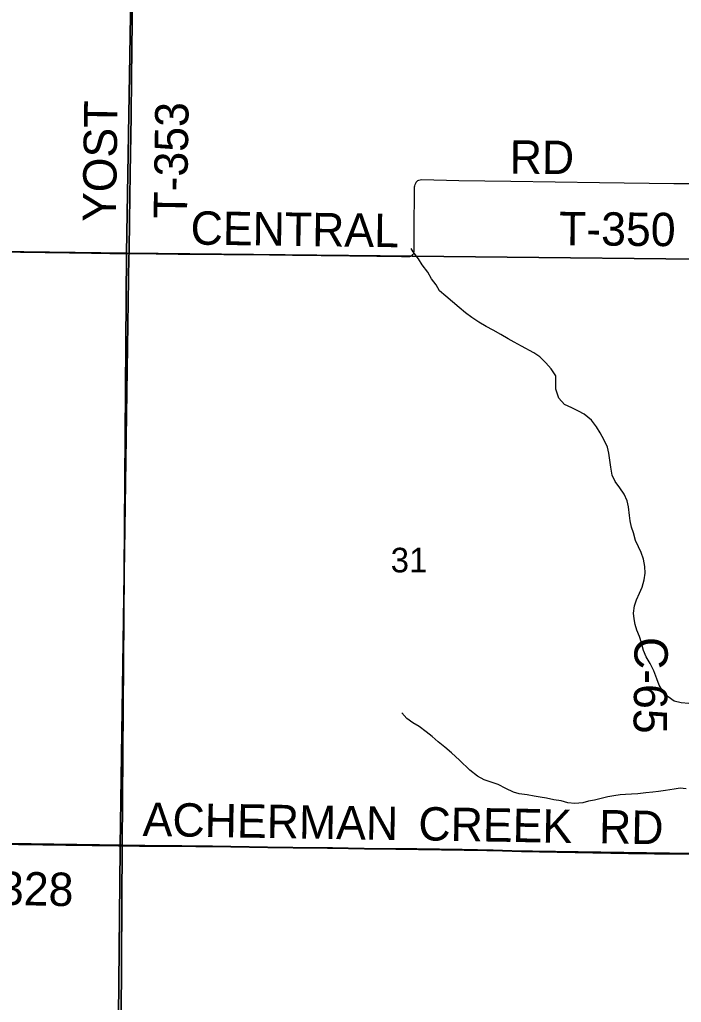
# Model space of a CAD drawing. Extents: x 0 to 34, y 0 to 22.
# Drawn here: x 3.317 to 4.443, y 18.105 to 19.778 of the extents above; entities that cross this region are included whole.
import ezdxf

# ---------------------------------------------------------------- set-up
doc = ezdxf.new("R2010")
doc.units = 0
for name, color, linetype in [('GM_X_Corporation', 7, 'Continuous'), ('GM_X_County_Road_Text', 7, 'Continuous'), ('GM_X_Minor_River', 7, 'Continuous'), ('GM_X_Section_Text', 7, 'Continuous'), ('GM_X_Township_Road', 7, 'Continuous'), ('GM_X_Township_Road_Text', 7, 'Continuous')]:
    doc.layers.add(name, color=color, linetype=linetype)

msp = doc.modelspace()

# ---------------------------------------------------------------- linework, layer by layer
at = {"layer": 'GM_X_Corporation'}
for points in [[(2.5086, 20.3801), (3.5147, 20.359), (3.4987, 19.3808), (2.4933, 19.3936)], [(3.5146, 20.3904), (4.4842, 20.3804), (4.4706, 19.3704), (3.4987, 19.3808), (3.5147, 20.359)], [(3.4987, 19.3808), (3.4912, 18.3726), (2.4847, 18.3876), (2.4733, 18.3879), (2.4933, 19.3936)], [(4.4706, 19.3704), (4.4615, 18.3587), (3.4912, 18.3726), (3.4987, 19.3808)], [(2.4847, 18.3876), (3.4912, 18.3726), (3.4847, 17.2912), (2.4791, 17.2994)], [(3.4912, 18.3726), (4.4615, 18.3587), (4.4872, 18.3578), (4.475, 17.2762), (3.4847, 17.2912)]]:
    msp.add_lwpolyline(points, close=True, dxfattribs=at)
for points in [[(3.2311, 18.3758), (3.3557, 18.374), (3.3947, 18.3734), (3.4864, 18.3719), (3.4876, 18.3718), (3.5027, 19.3746), (3.5028, 19.3803), (3.5029, 19.3859), (3.5036, 19.435), (3.5046, 19.517), (3.5062, 19.6139), (3.5072, 19.6797), (3.5082, 19.7748), (3.5095, 19.8637)], [(3.5095, 19.8637), (3.5082, 19.7748), (3.5072, 19.6797), (3.5062, 19.6139), (3.5046, 19.517), (3.5036, 19.435), (3.5029, 19.3859), (3.5028, 19.3803), (3.5027, 19.3746), (3.4876, 18.3718), (3.5205, 18.3717), (3.5734, 18.3714), (3.5926, 18.3714), (3.6162, 18.3712), (3.6448, 18.3709), (3.7386, 18.3694), (3.7818, 18.3688), (3.815, 18.3684), (3.8492, 18.368), (3.9032, 18.367), (3.9927, 18.3663), (4.0697, 18.3651), (4.1225, 18.3639), (4.1704, 18.3626), (4.353, 18.3592), (4.3971, 18.3585), (4.4651, 18.3578)], [(3.4672, 16.2781), (3.4754, 17.1134), (3.4875, 18.3666), (3.4876, 18.3718), (3.4864, 18.3719), (3.3947, 18.3734), (3.3557, 18.374), (3.2311, 18.3758)], [(4.4651, 18.3578), (4.3971, 18.3585), (4.353, 18.3592), (4.1704, 18.3626), (4.1225, 18.3639), (4.0697, 18.3651), (3.9927, 18.3663), (3.9032, 18.367), (3.8492, 18.368), (3.815, 18.3684), (3.7818, 18.3688), (3.7386, 18.3694), (3.6448, 18.3709), (3.6162, 18.3712), (3.5926, 18.3714), (3.5734, 18.3714), (3.5205, 18.3717), (3.4876, 18.3718), (3.4875, 18.3666), (3.4754, 17.1134)]]:
    msp.add_lwpolyline(points, dxfattribs=at)
at = {"layer": 'GM_X_Minor_River'}
for points in [[(4.3197, 19.0403), (4.3172, 19.0502), (4.3117, 19.0621), (4.3047, 19.0744), (4.2985, 19.0851), (4.29, 19.0963), (4.2776, 19.1063), (4.2679, 19.1118), (4.2562, 19.1174), (4.2438, 19.1229), (4.2341, 19.1337), (4.2291, 19.149), (4.2295, 19.1717), (4.2214, 19.1836), (4.2121, 19.1937), (4.202, 19.2041), (4.1919, 19.2111), (4.1709, 19.2221), (4.1585, 19.2288), (4.1479, 19.2347), (4.1359, 19.2421), (4.1224, 19.2492), (4.1104, 19.2559), (4.0984, 19.2633), (4.086, 19.2711), (4.0755, 19.2789), (4.0647, 19.2882), (4.0531, 19.2975), (4.0423, 19.3072), (4.0311, 19.3165), (4.0256, 19.3265), (4.0178, 19.3368), (4.0112, 19.348), (4.0019, 19.3607), (3.9956, 19.371), (3.9864, 19.3826), (3.9831, 19.3883)], [(4.4556, 18.6138), (4.4423, 18.6148), (4.4306, 18.6177), (4.4202, 18.6254), (4.4116, 18.6351), (4.405, 18.6451), (4.4014, 18.6561), (4.3963, 18.6695), (4.3897, 18.6818), (4.3831, 18.6933), (4.3787, 18.7043), (4.3752, 18.7173), (4.3716, 18.728), (4.3672, 18.7387), (4.364, 18.7486), (4.3623, 18.7581), (4.3617, 18.7676), (4.3634, 18.7801), (4.3667, 18.7906), (4.3714, 18.8019), (4.3762, 18.8117), (4.3798, 18.8242), (4.3812, 18.8359), (4.381, 18.8473), (4.3786, 18.8595), (4.3746, 18.8709), (4.3698, 18.8805), (4.3651, 18.8916), (4.3612, 18.9045), (4.3583, 18.9141), (4.3555, 18.9247), (4.3545, 18.9342), (4.3529, 18.9487), (4.3504, 18.959), (4.3453, 18.9701), (4.3379, 18.9812), (4.3305, 18.9916), (4.325, 19.0027), (4.323, 19.016), (4.321, 19.0282), (4.3197, 19.0403)], [(4.451, 18.4686), (4.4408, 18.4696), (4.4309, 18.4682), (4.4161, 18.4655), (4.4039, 18.4638), (4.3944, 18.4628), (4.3822, 18.4615), (4.3689, 18.4603), (4.3579, 18.4593), (4.348, 18.4588), (4.3385, 18.4582), (4.3279, 18.4565), (4.3176, 18.4552), (4.3062, 18.452), (4.2951, 18.4495), (4.2848, 18.4474), (4.2753, 18.4449), (4.2616, 18.4437), (4.2499, 18.445), (4.2382, 18.4479), (4.2261, 18.45), (4.2132, 18.4525), (4.2026, 18.4542), (4.1924, 18.4563), (4.1807, 18.4584), (4.1671, 18.4602), (4.1573, 18.463), (4.1441, 18.4694), (4.1309, 18.4757), (4.1177, 18.4805), (4.1075, 18.4837), (4.0959, 18.4903), (4.0828, 18.5001), (4.0653, 18.5174), (4.0519, 18.5298), (4.0403, 18.5395), (4.0287, 18.5485), (4.019, 18.5574), (4.0085, 18.5659), (3.9965, 18.5745), (3.9856, 18.5807), (3.9755, 18.5881), (3.9674, 18.5981)]]:
    msp.add_lwpolyline(points, dxfattribs=at)
at = {"layer": 'GM_X_Township_Road'}
for points in [[(3.5031, 19.3798), (3.5032, 19.3854), (3.5038, 19.4345), (3.5048, 19.5165), (3.5064, 19.6133), (3.5074, 19.6792), (3.5085, 19.7743), (3.5098, 19.8632), (3.5112, 19.9487), (3.5114, 20.0048), (3.5127, 20.0731), (3.5139, 20.1338), (3.5147, 20.2328), (3.5157, 20.313), (3.5165, 20.3521), (3.5172, 20.4142), (3.5183, 20.4919), (3.5194, 20.5485), (3.5199, 20.5944), (3.5206, 20.6629), (3.5216, 20.7379), (3.5226, 20.8342), (3.523, 20.8659), (3.5234, 20.9)], [(3.5031, 19.3798), (3.5118, 19.3797), (3.5864, 19.3791), (3.7417, 19.3776), (3.7811, 19.377), (3.8784, 19.3758), (3.9243, 19.3756), (3.9665, 19.375), (3.9779, 19.3747), (3.9805, 19.375), (3.9826, 19.3756), (3.9845, 19.3767), (3.9859, 19.3782), (3.9868, 19.3794), (3.9874, 19.3807), (3.9876, 19.382), (3.9879, 19.3834), (3.9882, 19.3851), (3.9882, 19.3907), (3.9883, 19.4181), (3.9885, 19.492), (3.9887, 19.4934), (3.989, 19.4951), (3.9896, 19.4975), (3.9907, 19.4997), (3.9918, 19.5015), (3.993, 19.5029), (3.9944, 19.504), (3.9962, 19.5047), (3.9981, 19.5054), (4.0005, 19.5058), (4.0644, 19.5044), (4.1528, 19.5034), (4.3037, 19.501), (4.4299, 19.4993), (4.467, 19.4994)], [(2.842, 19.385), (2.8468, 19.3865), (2.8511, 19.3878), (2.8558, 19.3889), (2.8794, 19.3883), (2.9819, 19.3867), (3.0658, 19.3854), (3.1527, 19.3839), (3.2136, 19.3834), (3.318, 19.3825), (3.4012, 19.3812), (3.4391, 19.3807), (3.4702, 19.3801), (3.5031, 19.3798)], [(3.1124, 18.3769), (3.1431, 18.3763), (3.1539, 18.3762), (3.1935, 18.3757), (3.2314, 18.3752), (3.3559, 18.3734), (3.395, 18.3729), (3.4846, 18.3714)], [(3.4846, 18.3714), (3.4866, 18.3713), (3.4872, 18.3713)], [(3.4872, 18.3713), (3.4878, 18.3713), (3.5208, 18.3712), (3.5736, 18.3709), (3.5929, 18.3709), (3.6165, 18.3706), (3.645, 18.3704), (3.7389, 18.3688), (3.782, 18.3683), (3.8153, 18.3679), (3.8494, 18.3674), (3.9035, 18.3665), (3.9929, 18.3658), (4.07, 18.3646), (4.1228, 18.3634), (4.1706, 18.3621), (4.3532, 18.3587), (4.3974, 18.358), (4.4712, 18.3572)]]:
    msp.add_lwpolyline(points, dxfattribs=at)

# ---------------------------------------------------------------- texts
at = {"layer": 'GM_X_County_Road_Text'}
msp.add_text('C-65', height=0.05682, rotation=269.3142, dxfattribs=at).set_placement((4.3633, 18.7274))
at = {"layer": 'GM_X_Section_Text'}
msp.add_text('31', height=0.04186, rotation=0, dxfattribs=at).set_placement((3.9482, 18.8371))
at = {"layer": 'GM_X_Township_Road_Text'}
for s, rotation, p in [('YOST', 89.2115, (3.4805, 19.4332)), ('T-353', 89.1574, (3.6014, 19.4389)), ('RD', 359.5064, (4.1505, 19.516)), ('CENTRAL', 359.2544, (3.6073, 19.3952)), ('T-350', 359.4386, (4.2344, 19.3942)), ('ACHERMAN', 359.0392, (3.5257, 18.3885)), ('CREEK', 358.988, (3.9949, 18.381)), ('RD', 359.0118, (4.3024, 18.376)), ('T-328', 358.8768, (3.2092, 18.2726))]:
    msp.add_text(s, height=0.05682, rotation=rotation, dxfattribs=at).set_placement(p)

doc.saveas('drawing.dxf')
